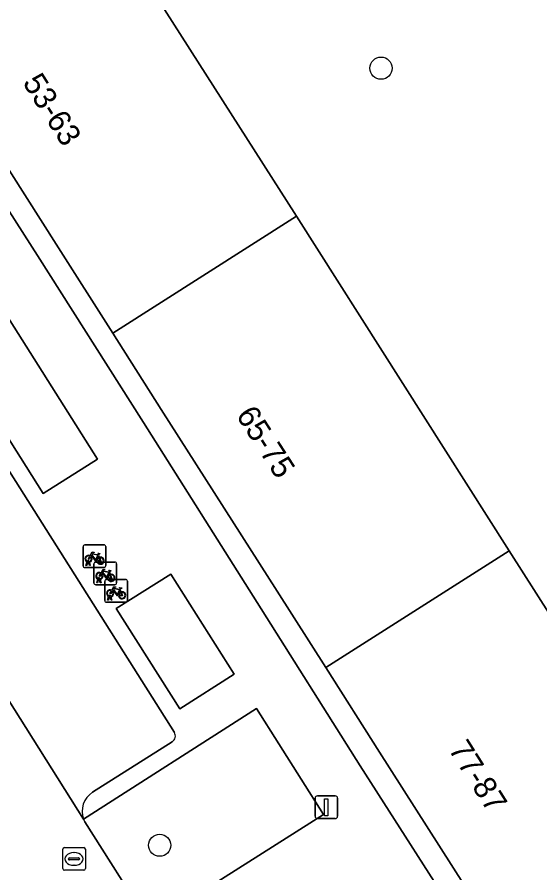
# Model space of a CAD drawing. Extents: x 162344 to 162869, y 381217 to 381818.
# Drawn here: x 162567.92 to 162590.99, y 381502.19 to 381539.96 of the extents above; entities that cross this region are included whole.
import ezdxf

# ---------------------------------------------------------------- set-up
doc = ezdxf.new("R2010")
doc.units = 0
for name, color, linetype in [('IMGEO_Boom', 7, 'Continuous'), ('IMGEO_Erf', 7, 'Continuous'), ('IMGEO_Fietsenrek', 7, 'Continuous'), ('IMGEO_Groenvoorziening', 7, 'Continuous'), ('IMGEO_Lichtmast', 7, 'Continuous'), ('IMGEO_Pand', 7, 'Continuous'), ('IMGEO_Pand_nummerreeks', 7, 'Continuous'), ('IMGEO_Parkeervlak_open', 7, 'Continuous'), ('IMGEO_Rijbaan_lokaal_open', 7, 'Continuous'), ('IMGEO_Rioolput', 7, 'Continuous'), ('IMGEO_Voetpad_open', 7, 'Continuous')]:
    doc.layers.add(name, color=color, linetype=linetype)

msp = doc.modelspace()

# ---------------------------------------------------------------- linework, layer by layer
at = {"layer": 'IMGEO_Boom'}
for centre in [(162583.981, 381537.711), (162574.214, 381503.415)]:
    msp.add_circle(centre, 0.489, dxfattribs=at)
at = {"layer": 'IMGEO_Erf'}
msp.add_lwpolyline([(162574.282, 381522.65), (162572.139, 381526.015), (162569.639, 381529.94), (162564.99, 381537.239), (162562.738, 381540.775), (162561.844, 381540.188), (162564.167, 381536.701), (162568.826, 381529.447), (162573.5, 381522.067), (162578.52, 381514.13), (162583.065, 381506.926), (162587.839, 381499.445), (162590.152, 381495.869), (162590.956, 381496.468), (162588.707, 381500), (162583.92, 381507.516), (162581.539, 381511.254), (162579.393, 381514.624)], close=True, dxfattribs=at)
at = {"layer": 'IMGEO_Fietsenrek'}
for p, q in [((162570.83, 381515.746), (162570.83, 381516.587)), ((162570.83, 381516.587), (162570.83, 381515.746)), ((162570.905, 381516.671), (162571.746, 381516.671)), ((162571.746, 381516.671), (162570.905, 381516.671)), ((162571.83, 381516.596), (162571.83, 381515.755)), ((162571.83, 381515.755), (162571.83, 381516.596)), ((162571.517, 381516.22), (162571.553, 381516.125)), ((162570.957, 381515.755), (162570.996, 381515.915)), ((162570.991, 381515.755), (162570.957, 381515.755)), ((162571.026, 381515.903), (162570.991, 381515.755)), ((162571.068, 381515.927), (162571.067, 381515.931)), ((162571.109, 381515.755), (162571.075, 381515.897)), ((162571.099, 381515.938), (162571.1, 381515.931)), ((162571.107, 381515.901), (162571.142, 381515.755)), ((162571.142, 381515.755), (162571.109, 381515.755)), ((162571.311, 381514.988), (162571.311, 381515.829)), ((162571.311, 381515.829), (162571.311, 381514.988)), ((162571.386, 381515.913), (162572.227, 381515.913)), ((162572.227, 381515.913), (162571.386, 381515.913)), ((162572.311, 381515.838), (162572.311, 381514.997)), ((162572.311, 381514.997), (162572.311, 381515.838)), ((162571.755, 381515.671), (162570.914, 381515.671)), ((162570.914, 381515.671), (162571.755, 381515.671)), ((162571.998, 381515.462), (162572.034, 381515.367)), ((162571.438, 381514.997), (162571.477, 381515.157)), ((162571.472, 381514.997), (162571.438, 381514.997)), ((162571.507, 381515.145), (162571.472, 381514.997)), ((162571.549, 381515.169), (162571.548, 381515.173)), ((162571.59, 381514.997), (162571.556, 381515.139)), ((162571.58, 381515.18), (162571.581, 381515.173)), ((162571.588, 381515.143), (162571.623, 381514.997)), ((162571.623, 381514.997), (162571.59, 381514.997)), ((162571.786, 381514.22), (162571.786, 381515.061)), ((162571.786, 381515.061), (162571.786, 381514.22)), ((162571.861, 381515.145), (162572.702, 381515.145)), ((162572.702, 381515.145), (162571.861, 381515.145)), ((162572.786, 381515.07), (162572.786, 381514.229)), ((162572.786, 381514.229), (162572.786, 381515.07)), ((162572.236, 381514.913), (162571.395, 381514.913)), ((162571.395, 381514.913), (162572.236, 381514.913)), ((162572.473, 381514.694), (162572.509, 381514.599)), ((162571.913, 381514.229), (162571.952, 381514.389)), ((162571.947, 381514.229), (162571.913, 381514.229)), ((162571.982, 381514.377), (162571.947, 381514.229)), ((162572.024, 381514.401), (162572.023, 381514.405)), ((162572.065, 381514.229), (162572.031, 381514.371)), ((162572.055, 381514.412), (162572.056, 381514.405)), ((162572.063, 381514.375), (162572.098, 381514.229)), ((162572.098, 381514.229), (162572.065, 381514.229)), ((162572.711, 381514.145), (162571.87, 381514.145)), ((162571.87, 381514.145), (162572.711, 381514.145))]:
    msp.add_line(p, q, dxfattribs=at)
for points in [[(162571.164, 381516.145), (162571.112, 381516.055), (162571.072, 381516.03), (162571.073, 381516.077), (162571.128, 381516.171)], [(162571.143, 381516.197), (162571.238, 381516.361), (162571.324, 381516.347), (162571.326, 381516.338), (162571.27, 381516.327), (162571.243, 381516.282), (162571.499, 381516.241)], [(162571.439, 381515.953), (162571.389, 381515.953), (162571.198, 381516.204), (162571.179, 381516.172)], [(162571.486, 381516.216), (162571.229, 381516.257), (162571.212, 381516.228), (162571.379, 381516.008), (162571.486, 381516.216)], [(162571.534, 381516.118), (162571.504, 381516.195), (162571.395, 381515.977), (162571.438, 381515.977)], [(162571.468, 381515.977), (162571.588, 381515.976), (162571.544, 381516.09)], [(162571.564, 381516.097), (162571.619, 381515.952), (162571.469, 381515.952)], [(162571.499, 381516.241), (162571.524, 381516.29), (162571.518, 381516.294), (162571.495, 381516.298), (162571.483, 381516.305), (162571.482, 381516.308), (162571.484, 381516.313), (162571.579, 381516.298), (162571.581, 381516.288), (162571.571, 381516.275), (162571.559, 381516.269), (162571.545, 381516.275), (162571.517, 381516.22)], [(162571.645, 381515.387), (162571.593, 381515.297), (162571.553, 381515.272), (162571.554, 381515.319), (162571.609, 381515.413)], [(162571.624, 381515.439), (162571.719, 381515.603), (162571.805, 381515.589), (162571.807, 381515.58), (162571.751, 381515.569), (162571.724, 381515.524), (162571.98, 381515.483)], [(162571.92, 381515.195), (162571.87, 381515.195), (162571.679, 381515.446), (162571.66, 381515.414)], [(162571.967, 381515.458), (162571.71, 381515.499), (162571.693, 381515.47), (162571.86, 381515.25), (162571.967, 381515.458)], [(162572.015, 381515.36), (162571.985, 381515.437), (162571.876, 381515.219), (162571.919, 381515.219)], [(162571.949, 381515.219), (162572.069, 381515.218), (162572.025, 381515.332)], [(162572.045, 381515.339), (162572.1, 381515.194), (162571.95, 381515.194)], [(162571.98, 381515.483), (162572.005, 381515.532), (162571.999, 381515.536), (162571.976, 381515.54), (162571.964, 381515.547), (162571.963, 381515.55), (162571.965, 381515.555), (162572.06, 381515.54), (162572.062, 381515.53), (162572.052, 381515.517), (162572.04, 381515.511), (162572.026, 381515.517), (162571.998, 381515.462)], [(162572.12, 381514.619), (162572.068, 381514.529), (162572.028, 381514.504), (162572.029, 381514.551), (162572.084, 381514.645)], [(162572.099, 381514.671), (162572.194, 381514.835), (162572.28, 381514.821), (162572.282, 381514.812), (162572.226, 381514.801), (162572.199, 381514.756), (162572.455, 381514.715)], [(162572.395, 381514.427), (162572.345, 381514.427), (162572.154, 381514.678), (162572.135, 381514.646)], [(162572.442, 381514.69), (162572.185, 381514.731), (162572.168, 381514.702), (162572.335, 381514.482), (162572.442, 381514.69)], [(162572.49, 381514.592), (162572.46, 381514.669), (162572.351, 381514.451), (162572.394, 381514.451)], [(162572.424, 381514.451), (162572.544, 381514.45), (162572.5, 381514.564)], [(162572.52, 381514.571), (162572.575, 381514.426), (162572.425, 381514.426)], [(162572.455, 381514.715), (162572.48, 381514.764), (162572.474, 381514.768), (162572.451, 381514.772), (162572.439, 381514.779), (162572.438, 381514.782), (162572.44, 381514.787), (162572.535, 381514.772), (162572.537, 381514.762), (162572.527, 381514.749), (162572.515, 381514.743), (162572.501, 381514.749), (162572.473, 381514.694)]]:
    msp.add_lwpolyline(points, dxfattribs=at)
for centre, radius, start, end in [((162570.908, 381516.593), 0.0779, 92.4484, 184.2845), ((162570.908, 381516.593), 0.0779, 92.4484, 184.2845), ((162571.752, 381516.593), 0.0779, 2.4484, 94.2845), ((162571.752, 381516.593), 0.0779, 2.4484, 94.2845), ((162571.07, 381516.056), 0.159, 62.6766, 242.1369), ((162571.07, 381516.056), 0.129, 63.3192, 238.903), ((162571.07, 381516.056), 0.129, 283.6043, 43.4302), ((162571.07, 381516.056), 0.159, 283.5766, 46.6042), ((162571.597, 381515.972), 0.159, 113.3408, 178.3217), ((162571.597, 381515.972), 0.159, 187.0065, 105.7708), ((162571.597, 381515.972), 0.129, 113.923, 177.9556), ((162571.597, 381515.972), 0.129, 188.6715, 104.5883), ((162570.908, 381515.749), 0.0779, 182.4484, 274.2845), ((162570.908, 381515.749), 0.0779, 182.4484, 274.2845), ((162571.05, 381515.927), 0.0499, 12.8025, 158.6934), ((162571.07, 381516.056), 0.159, 253.9967, 271.7867), ((162571.05, 381515.927), 0.0174, 12.8025, 163.4502), ((162571.07, 381516.056), 0.129, 253.415, 269.0204), ((162571.389, 381515.835), 0.0779, 92.4484, 184.2845), ((162571.389, 381515.835), 0.0779, 92.4484, 184.2845), ((162571.752, 381515.749), 0.0779, 272.4484, 4.2845), ((162571.752, 381515.749), 0.0779, 272.4484, 4.2845), ((162572.233, 381515.835), 0.0779, 2.4484, 94.2845), ((162572.233, 381515.835), 0.0779, 2.4484, 94.2845), ((162571.551, 381515.298), 0.159, 62.6766, 242.1369), ((162571.551, 381515.298), 0.129, 63.3192, 238.903), ((162571.551, 381515.298), 0.129, 283.6043, 43.4302), ((162571.551, 381515.298), 0.159, 283.5766, 46.6042), ((162572.078, 381515.214), 0.159, 113.3408, 178.3217), ((162572.078, 381515.214), 0.159, 187.0065, 105.7708), ((162572.078, 381515.214), 0.129, 113.923, 177.9556), ((162572.078, 381515.214), 0.129, 188.6715, 104.5883), ((162571.389, 381514.991), 0.0779, 182.4484, 274.2845), ((162571.389, 381514.991), 0.0779, 182.4484, 274.2845), ((162571.531, 381515.169), 0.0499, 12.8025, 158.6934), ((162571.551, 381515.298), 0.159, 253.9967, 271.7867), ((162571.531, 381515.169), 0.0174, 12.8025, 163.4502), ((162571.551, 381515.298), 0.129, 253.415, 269.0204), ((162571.864, 381515.067), 0.0779, 92.4484, 184.2845), ((162571.864, 381515.067), 0.0779, 92.4484, 184.2845), ((162572.233, 381514.991), 0.0779, 272.4484, 4.2845), ((162572.233, 381514.991), 0.0779, 272.4484, 4.2845), ((162572.708, 381515.067), 0.0779, 2.4484, 94.2845), ((162572.708, 381515.067), 0.0779, 2.4484, 94.2845), ((162572.026, 381514.53), 0.159, 62.6766, 242.1369), ((162572.026, 381514.53), 0.129, 63.3192, 238.903), ((162572.026, 381514.53), 0.129, 283.6043, 43.4302), ((162572.026, 381514.53), 0.159, 283.5766, 46.6042), ((162572.553, 381514.446), 0.159, 113.3408, 178.3217), ((162572.553, 381514.446), 0.159, 187.0065, 105.7708), ((162572.553, 381514.446), 0.129, 113.923, 177.9556), ((162572.553, 381514.446), 0.129, 188.6715, 104.5883), ((162571.864, 381514.223), 0.0779, 182.4484, 274.2845), ((162571.864, 381514.223), 0.0779, 182.4484, 274.2845), ((162572.006, 381514.401), 0.0499, 12.8025, 158.6934), ((162572.026, 381514.53), 0.159, 253.9967, 271.7867), ((162572.006, 381514.401), 0.0174, 12.8025, 163.4502), ((162572.026, 381514.53), 0.129, 253.415, 269.0204), ((162572.708, 381514.223), 0.0779, 272.4484, 4.2845), ((162572.708, 381514.223), 0.0779, 272.4484, 4.2845)]:
    msp.add_arc(centre, radius, start, end, dxfattribs=at)
at = {"layer": 'IMGEO_Groenvoorziening'}
msp.add_lwpolyline([(162570.842, 381545.936), (162580.243, 381531.175), (162589.643, 381516.415), (162599.059, 381501.63), (162600.915, 381500.002)], dxfattribs=at)
for points in [[(162569.074, 381518.934), (162571.468, 381520.451), (162565.153, 381530.43), (162562.774, 381528.908)], [(162575.097, 381509.44), (162577.506, 381510.972), (162574.698, 381515.383), (162572.291, 381513.869)], [(162581.439, 381504.773), (162578.487, 381509.446), (162570.854, 381504.569), (162570.91, 381504.449), (162573.691, 381500.063), (162573.732, 381500.011), (162573.805, 381499.933)]]:
    msp.add_lwpolyline(points, close=True, dxfattribs=at)
at = {"layer": 'IMGEO_Lichtmast'}
for p, q in [((162581.07, 381504.691), (162581.07, 381505.491)), ((162581.07, 381505.491), (162581.07, 381504.691)), ((162581.17, 381505.591), (162581.96, 381505.591)), ((162581.96, 381505.591), (162581.17, 381505.591)), ((162582.06, 381505.491), (162582.06, 381504.691)), ((162582.06, 381504.691), (162582.06, 381505.491)), ((162581.96, 381504.591), (162581.17, 381504.591)), ((162581.17, 381504.591), (162581.96, 381504.591))]:
    msp.add_line(p, q, dxfattribs=at)
msp.add_lwpolyline([(162581.49, 381505.466), (162581.64, 381505.466), (162581.64, 381504.716), (162581.49, 381504.716), (162581.49, 381505.466)], dxfattribs=at)
for centre, start, end in [((162581.17, 381505.491), 90, 180), ((162581.17, 381505.491), 90, 180), ((162581.96, 381505.491), 0, 90), ((162581.96, 381505.491), 360, 90), ((162581.17, 381504.691), 180, 270), ((162581.17, 381504.691), 180, 270), ((162581.96, 381504.691), 270, 0), ((162581.96, 381504.691), 270, 0)]:
    msp.add_arc(centre, 0.1, start, end, dxfattribs=at)
at = {"layer": 'IMGEO_Pand'}
for points in [[(162572.139, 381526.015), (162580.243, 381531.175), (162570.842, 381545.936), (162562.738, 381540.775), (162564.99, 381537.239), (162569.639, 381529.94)], [(162581.539, 381511.254), (162589.643, 381516.415), (162580.243, 381531.175), (162572.139, 381526.015), (162574.282, 381522.65), (162579.393, 381514.624)], [(162581.539, 381511.254), (162583.92, 381507.516), (162588.707, 381500), (162590.956, 381496.468), (162596.5, 381500), (162599.059, 381501.63), (162589.643, 381516.415)]]:
    msp.add_lwpolyline(points, close=True, dxfattribs=at)
at = {"layer": 'IMGEO_Parkeervlak_open'}
for points in [[(162574.862, 381508.393), (162560.74, 381530.71)], [(162555.463, 381529.008), (162570.854, 381504.569)], [(162571.249, 381505.751), (162574.762, 381507.981)]]:
    msp.add_lwpolyline(points, dxfattribs=at)
for centre, radius, start, end in [((162574.595, 381508.24), 0.308, 302.8247, 29.8895), ((162571.766, 381504.921), 0.978, 121.9189, 201.124)]:
    msp.add_arc(centre, radius, start, end, dxfattribs=at)
at = {"layer": 'IMGEO_Rijbaan_lokaal_open'}
msp.add_lwpolyline([(162555.463, 381529.008), (162554.627, 381530.33), (162554.129, 381531.117), (162554.011, 381531.312), (162550.129, 381528.868), (162550.23, 381528.711), (162550.801, 381527.797), (162551.625, 381526.479), (162551.711, 381526.315), (162564.479, 381506.132), (162564.586, 381505.98), (162571.159, 381495.615), (162575.133, 381489.296), (162579.561, 381482.257), (162583.279, 381484.807), (162583.17, 381484.957), (162579.723, 381490.44), (162579.695, 381490.504), (162573.732, 381500.011), (162573.691, 381500.063), (162570.91, 381504.449), (162570.854, 381504.569)], close=True, dxfattribs=at)
at = {"layer": 'IMGEO_Rioolput'}
for p, q in [((162569.931, 381502.386), (162569.931, 381503.238)), ((162570.006, 381503.312), (162570.858, 381503.312)), ((162570.932, 381503.238), (162570.932, 381502.386)), ((162570.233, 381502.855), (162570.631, 381502.855)), ((162570.419, 381503.092), (162570.444, 381503.092)), ((162570.19, 381502.806), (162570.19, 381502.818)), ((162570.628, 381502.769), (162570.23, 381502.769)), ((162570.442, 381502.532), (162570.417, 381502.532)), ((162570.674, 381502.818), (162570.674, 381502.806)), ((162570.858, 381502.312), (162570.006, 381502.312))]:
    msp.add_line(p, q, dxfattribs=at)
for points in [[(162569.931, 381502.386), (162569.931, 381503.238)], [(162570.006, 381503.312), (162570.858, 381503.312)], [(162570.932, 381503.238), (162570.932, 381502.386)], [(162570.858, 381502.312), (162570.006, 381502.312)]]:
    msp.add_lwpolyline(points, dxfattribs=at)
for centre, radius, start, end in [((162570.008, 381503.236), 0.0765, 91.552, 178.448), ((162570.008, 381503.236), 0.0765, 91.552, 178.448), ((162570.856, 381503.236), 0.0765, 1.552, 88.448), ((162570.856, 381503.236), 0.0765, 1.552, 88.448), ((162570.23, 381502.815), 0.0403, 85.8775, 175.7526), ((162570.635, 381502.817), 0.0386, 1.7309, 96.639), ((162570.227, 381502.805), 0.0366, 178.938, 274.7102), ((162570.631, 381502.812), 0.043, 264.8664, 352.4533), ((162570.008, 381502.388), 0.0765, 181.552, 268.448), ((162570.008, 381502.388), 0.0765, 181.552, 268.448), ((162570.856, 381502.388), 0.0765, 271.552, 358.448), ((162570.856, 381502.388), 0.0765, 271.552, 358.448)]:
    msp.add_arc(centre, radius, start, end, dxfattribs=at)
for centre, major_axis, ratio, start_param, end_param in [((162570.418, 381502.812), (-0.387, 0.002), 0.722429, 4.712389, 7.853982), ((162570.443, 381502.812), (-0.39, 0.002), 0.717154, 1.570796, 4.712389)]:
    msp.add_ellipse(centre, major_axis=major_axis, ratio=ratio, start_param=start_param, end_param=end_param, dxfattribs=at)
at = {"layer": 'IMGEO_Voetpad_open'}
for points in [[(162597.177, 381488.01), (162596.332, 381488.956), (162590.152, 381495.869), (162587.839, 381499.445), (162583.065, 381506.926), (162578.52, 381514.13), (162573.5, 381522.067), (162568.826, 381529.447), (162564.167, 381536.701)], [(162560.74, 381530.71), (162574.862, 381508.393)], [(162570.854, 381504.569), (162578.487, 381509.446), (162581.439, 381504.773), (162573.805, 381499.933)], [(162574.762, 381507.981), (162571.249, 381505.751)]]:
    msp.add_lwpolyline(points, dxfattribs=at)
for points in [[(162565.153, 381530.43), (162571.468, 381520.451), (162569.074, 381518.934), (162562.774, 381528.908)], [(162574.698, 381515.383), (162577.506, 381510.972), (162575.097, 381509.44), (162572.291, 381513.869)]]:
    msp.add_lwpolyline(points, close=True, dxfattribs=at)
for centre, radius, start, end in [((162574.595, 381508.24), 0.308, 302.8247, 29.8895), ((162571.766, 381504.921), 0.978, 121.9189, 201.124)]:
    msp.add_arc(centre, radius, start, end, dxfattribs=at)

# ---------------------------------------------------------------- texts
at = {"layer": 'IMGEO_Pand_nummerreeks'}
for s, rotation, p in [('53-63', 302.2906, (162568.137, 381537.075)), ('65-75', 302.7555, (162577.556, 381522.393)), ('77-87', 302.2906, (162586.932, 381507.649))]:
    msp.add_text(s, height=1, rotation=rotation, dxfattribs=at).set_placement(p)

doc.saveas('drawing.dxf')
